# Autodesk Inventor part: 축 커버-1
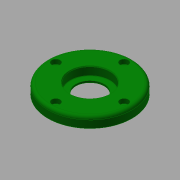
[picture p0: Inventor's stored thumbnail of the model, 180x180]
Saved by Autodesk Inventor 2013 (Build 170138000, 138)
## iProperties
Created: 2015-10
Part Number: 축 커버-1
Document SubType Name: Modeling
Designer: mdu
Density: 1 g/cm^3
Material: 강철, 연강
Author: mdu
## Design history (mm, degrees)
sketch "스케치1"
  geometry: C1 r 40 at (0, 0) reference; C2 r 26 at (0, 0) reference; 1 further point
  node "참조1"
  node "참조2"
extrude "돌출1" new body sketch "스케치1" distance "d0" = 10; taper "d1" = 0 deg
extrude "돌출2" join sketch "스케치1" distance "d2" = 3; taper "d3" = 0 deg
hole "구멍1" diameter "d6" = 27; stored, may be unused: countersink angle "d10" = 90 deg, drill point angle "d12" = 118 deg; dims "d7" = 6, "d8" = 38, "d9" = 8.3, "d11" = 8, "d31" = 10, "d32" = 10
sketch "스케치2"
  geometry: C1 r 20 at (0, 0); 1 further point
  constraints: 1 centre point, 1 coincident
  dimensions: "d13" = 40 diameter of C1
extrude "돌출3" cut sketch "스케치2" distance "d14" = 3; taper "d15" = 0 deg
sketch "스케치3"
  geometry: C1 r 1.621 at (0, 32.5) reference; 1 further point
hole "구멍2" sketch "스케치3" at (0, 32.5) diameter "d16" = 4.5; stored, may be unused: countersink angle "d20" = 90 deg, drill point angle "d22" = 118 deg; dims "d17" = 6, "d18" = 8, "d19" = 4.4, "d21" = 8
fillet "모깎기1" dims "d26" = 3, "d27" = 0.3
chamfer "모따기1" distance "d28" = 1; stored, may be unused: second distance "d29" = 2, angle "d30" = 45 deg
chamfer "모따기2" distance "d33" = 0.8; stored, may be unused: second distance "d34" = 2, angle "d35" = 30 deg
node "솔리드1"
pattern_circular "원형 패턴1" dims angle "d24" = 360 deg
node "참조3"
